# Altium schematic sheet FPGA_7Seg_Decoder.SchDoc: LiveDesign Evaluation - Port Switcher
size A4; Organization: Altium Limited; Address1: L3, 12a Rodborough Rd; Address2: Frenchs Forest; Address3: NSW; Address4: Australia 2086
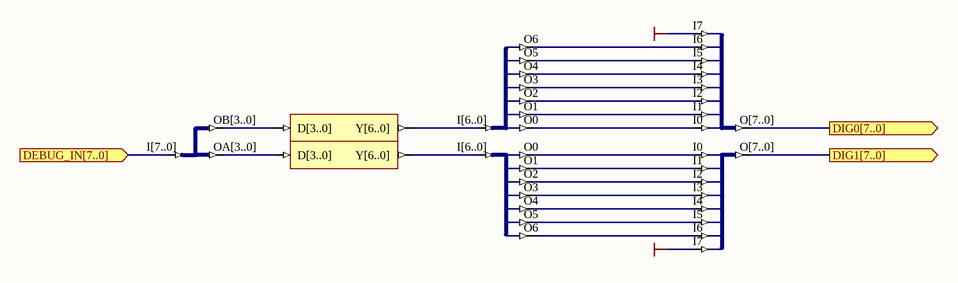
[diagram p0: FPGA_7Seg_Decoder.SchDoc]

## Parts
U17  J8S_8B  (value not drawn)
U18  J8S_8B  (value not drawn)
U23  J7B_7S  (value not drawn)
U24  J7B_7S  (value not drawn)
U28  D7SEGB  (value not drawn)
U29  D7SEGB  (value not drawn)
U32  J8B_4B2  (value not drawn)

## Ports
DEBUG_IN[7..0] (in), DIG0[7..0] (out), DIG1[7..0] (out)

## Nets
GND: U17.I7 U18.I7
NetU17_I0: U17.I0 U23.O0
NetU17_I1: U17.I1 U23.O1
NetU17_I2: U17.I2 U23.O2
NetU17_I3: U17.I3 U23.O3
NetU17_I4: U17.I4 U23.O4
NetU17_I5: U17.I5 U23.O5
NetU17_I6: U17.I6 U23.O6
NetU18_I0: U18.I0 U24.O0
NetU18_I1: U18.I1 U24.O1
NetU18_I2: U18.I2 U24.O2
NetU18_I3: U18.I3 U24.O3
NetU18_I4: U18.I4 U24.O4
NetU18_I5: U18.I5 U24.O5
NetU18_I6: U18.I6 U24.O6

Not connected (* = marked no-connect by the designer): U17 O[7..0]; U18 O[7..0]; U23 I[6..0]; U24 I[6..0]; U28 D[3..0] Y[6..0]; U29 D[3..0] Y[6..0]; U32 I[7..0] OA[3..0] OB[3..0]

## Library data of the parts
U17 U18 = J8S_8B: 8 Single pin inputs to single 8-Bit output bus; ArchiveName: GENERIC; VHDLIB_SIM: GENERIC_LIB
U23 U24 = J7B_7S: 7-Bit input bus to 7 Single pin outputs; ArchiveName: GENERIC; VHDLIB_SIM: GENERIC_LIB
U28 U29 = D7SEGB: 7-Segment-Display Decoder for Common-Cathode LED (Active High Output), Bus Version; ArchiveName: GENERIC; VHDLIB_SIM: GENERIC_LIB
U32 = J8B_4B2: 1 x 8-bit input bus to 2 x 4-Bit output bus; ArchiveName: GENERIC; VHDLIB_SIM: GENERIC_LIB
